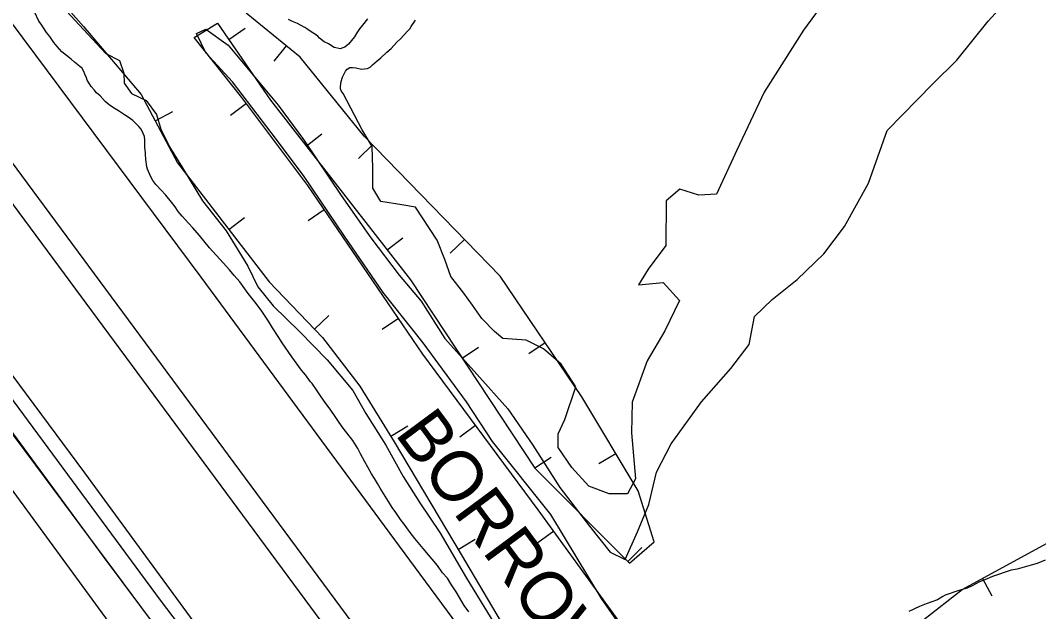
# Model space of a CAD drawing. Extents: x 3263578 to 3301413, y 764927 to 798602.
# Drawn here: x 3286141 to 3287429, y 776533 to 777281 of the extents above; entities that cross this region are included whole.
import ezdxf

# ---------------------------------------------------------------- set-up
doc = ezdxf.new("R2010")
doc.units = 0
for name, color, linetype in [('V-BORW-IDEN', 7, 'Continuous'), ('V-BORW-LINE', 7, 'Continuous'), ('V-LEVE-TOET', 7, 'Continuous'), ('V-ROAD-CNTR', 7, 'Continuous'), ('V-SITE-VEGE', 7, 'Continuous'), ('V-SURV-LINE', 7, 'Continuous'), ('V-TOPO-SHOR', 7, 'Continuous')]:
    doc.layers.add(name, color=color, linetype=linetype)

msp = doc.modelspace()

# ---------------------------------------------------------------- linework, layer by layer
at = {"layer": 'V-BORW-LINE'}
for p, q in [((3286405, 777256.5), (3286425.6, 777270.7)), ((3286477.5, 777248.5), (3286461.7, 777229.1)), ((3286427.2, 777175.5), (3286407.2, 777160.5)), ((3286311.9, 777153.7), (3286334, 777165.4)), ((3286502.8, 777121.8), (3286522.6, 777137.1)), ((3286586.7, 777123.2), (3286568.8, 777105.8)), ((3286525.7, 777041.2), (3286505.1, 777027.1)), ((3286404.9, 777016.1), (3286424.7, 777031.4)), ((3286605.1, 776990.3), (3286624.8, 777005.6)), ((3286702.8, 777003.7), (3286684.9, 776986.3)), ((3286513.4, 776890), (3286531.4, 776907.3)), ((3286619.6, 776903.6), (3286599, 776889.5)), ((3286699.9, 776853.4), (3286720.8, 776867.2)), ((3286805, 776873), (3286784.3, 776859)), ((3286609.9, 776754.7), (3286631.2, 776767.8)), ((3286717, 776768.4), (3286696.9, 776753.6)), ((3286791.8, 776714.5), (3286812.7, 776728.3)), ((3286894.3, 776732.4), (3286872.9, 776719.6)), ((3286815.9, 776634.4), (3286795.6, 776619.7)), ((3286695.1, 776611.5), (3286716.6, 776624.3)), ((3286909.3, 776596.4), (3286927.1, 776614)), ((3287357.8, 776574.7), (3287369.8, 776552.7))]:
    msp.add_line(p, q, dxfattribs=at)
for points in [[(3286160.4, 777342.2), (3286221.4, 777272.9), (3286294.3, 777187.1), (3286340, 777100.4), (3286455.8, 776950.1), (3286523.5, 776879.5), (3286570.8, 776818.2), (3286614.2, 776747.6), (3286698.9, 776605.2), (3286809.6, 776417.4), (3286922.6, 776297), (3287077.5, 776083.5)], [(3287004.7, 776373.8), (3286796.2, 776661.5), (3286650.4, 776858.3), (3286504.8, 777071.9), (3286421.6, 777183.1), (3286361, 777259.1), (3286390.8, 777277.2), (3286457.6, 777179.9), (3286634.5, 776952.5), (3286792.1, 776714.1), (3286911.7, 776594), (3286942.6, 776621), (3286922.4, 776685.4), (3286851.3, 776804.7), (3286748, 776957.2), (3286576.1, 777134.1), (3286495.3, 777234), (3286426.7, 777289.8)], [(3287635.8, 776864.5), (3287745.4, 777082.2), (3287849.5, 777197.7), (3287882.8, 777161.5), (3287924.8, 777006.7), (3287854.3, 776873.2), (3287839.2, 776817.4), (3287909.8, 776759.6), (3287906.6, 776694.7), (3287779.5, 776623.5), (3287722.3, 776563.9), (3287636.3, 776461.8), (3287511.2, 776403.8), (3287441.6, 776389.5), (3287347.5, 776365.9), (3287246.2, 776391.1), (3287218.3, 776420.9), (3287225.5, 776477.1), (3287332.4, 776560.9), (3287439.7, 776619.3), (3287525.1, 776691.8), (3287573.6, 776725.7), (3287635.8, 776864.5)]]:
    msp.add_lwpolyline(points, dxfattribs=at)
at = {"layer": 'V-LEVE-TOET'}
for points in [[(3284126.3, 779529.1), (3284162.9, 779488.4), (3284218.5, 779416.3), (3284353, 779234.8), (3284501.4, 779037.8), (3284646, 778841.6), (3284765.5, 778673.7), (3284949.2, 778430), (3285219, 778068), (3285459.2, 777737.5), (3285691.2, 777424.3), (3285965.8, 777054.1), (3286222.6, 776708.5), (3286385.9, 776484.8), (3286571.9, 776233.4), (3286758.9, 775979.6), (3286871.1, 775830.8)], [(3287161.8, 775830.9), (3287131.1, 775890.3), (3287046.7, 776024.8), (3286938.6, 776189.3), (3286930.1, 776200.3), (3286881.3, 776262.8), (3286620.6, 776615.7), (3286369.9, 776955.7), (3286114.9, 777297.8), (3285934.2, 777538), (3285840, 777634.2), (3285749.6, 777751.3), (3285729.7, 777777.6), (3285706.2, 777802.7), (3285684.1, 777829), (3285660.6, 777857.1), (3285622.8, 777919.3), (3285398.6, 778209.6)]]:
    msp.add_lwpolyline(points, dxfattribs=at)
at = {"layer": 'V-ROAD-CNTR'}
for points in [[(3286817.5, 775833.6), (3286161.1, 776718.1), (3285511.5, 777590.9), (3285032.8, 778237.4), (3284479.5, 778985.2), (3284180.8, 779387.8)], [(3285836.1, 777156.8), (3286022.5, 776906.7), (3286246.2, 776602.6), (3286504.3, 776256.5), (3286568.2, 776171)]]:
    msp.add_lwpolyline(points, dxfattribs=at)
at = {"layer": 'V-SITE-VEGE'}
for p, q in [((3287191.8, 777351), (3287131.4, 777268.3)), ((3287365.3, 777279.9), (3287395.2, 777313.6)), ((3286164.8, 777279.6), (3286159.2, 777291.6)), ((3286189.8, 777303.2), (3286221, 777269.1)), ((3286167.6, 777275.9), (3286164.8, 777279.6)), ((3286635.6, 777273), (3286641.1, 777280.9)), ((3287325.5, 777230.2), (3287365.3, 777279.9)), ((3286174.5, 777265.3), (3286167.6, 777275.9)), ((3286178.7, 777260.2), (3286174.5, 777265.3)), ((3286221, 777269.1), (3286249.3, 777238.9)), ((3286364, 777264.3), (3286375.8, 777269.7)), ((3286375.8, 777269.7), (3286404.1, 777249.5)), ((3286626.4, 777261.9), (3286631.4, 777267.5)), ((3286631.4, 777267.5), (3286633.7, 777270.2)), ((3286633.7, 777270.2), (3286635.6, 777273)), ((3287131.4, 777268.3), (3287081.9, 777189.9)), ((3286183.8, 777252.8), (3286178.7, 777260.2)), ((3286188, 777247.8), (3286183.8, 777252.8)), ((3286376.1, 777239.5), (3286364, 777264.3)), ((3286610.2, 777245.2), (3286617.6, 777253.1)), ((3286617.6, 777253.1), (3286622.2, 777257.3)), ((3286622.2, 777257.3), (3286626.4, 777261.9)), ((3286194, 777240.9), (3286188, 777247.8)), ((3286205.6, 777231.6), (3286194, 777240.9)), ((3286409.5, 777202.9), (3286376.1, 777239.5)), ((3286404.1, 777249.5), (3286467.2, 777173.5)), ((3286597.3, 777233.2), (3286604.7, 777240.6)), ((3286604.7, 777240.6), (3286610.2, 777245.2)), ((3286209.7, 777228), (3286205.6, 777231.6)), ((3286213.9, 777224.7), (3286209.7, 777228)), ((3286249.3, 777238.9), (3286266.6, 777229.8)), ((3286266.6, 777229.8), (3286272.3, 777213.8)), ((3286586.7, 777224.4), (3286592.7, 777229.5)), ((3286592.7, 777229.5), (3286597.3, 777233.2)), ((3287295, 777200.5), (3287325.5, 777230.2)), ((3286217.1, 777222), (3286213.9, 777224.7)), ((3286219, 777220.6), (3286217.1, 777222)), ((3286221.8, 777216), (3286219, 777220.6)), ((3286222.7, 777212.7), (3286221.8, 777216)), ((3286272.3, 777213.8), (3286272.7, 777201.3)), ((3286548.9, 777209), (3286552.6, 777216.4)), ((3286552.6, 777216.4), (3286554.4, 777219.2)), ((3286554.4, 777219.2), (3286558.1, 777221.1)), ((3286558.1, 777221.1), (3286561.3, 777221.1)), ((3286561.3, 777221.1), (3286565.5, 777220.6)), ((3286565.5, 777220.6), (3286572.9, 777219.2)), ((3286572.9, 777219.2), (3286576.1, 777219.3)), ((3286576.1, 777219.3), (3286580.3, 777219.7)), ((3286580.3, 777219.7), (3286583.5, 777221.6)), ((3286583.5, 777221.6), (3286586.7, 777224.4)), ((3286225, 777208.1), (3286222.7, 777212.7)), ((3286226, 777204.9), (3286225, 777208.1)), ((3286228.7, 777200.3), (3286226, 777204.9)), ((3286272.7, 777201.3), (3286281.9, 777188.3)), ((3286458.6, 777139), (3286409.5, 777202.9)), ((3286546.1, 777197), (3286547.1, 777203.5)), ((3286547.1, 777203.5), (3286548.9, 777209)), ((3286231.1, 777197.1), (3286228.7, 777200.3)), ((3286234.8, 777192.9), (3286231.1, 777197.1)), ((3286237.6, 777189.2), (3286234.8, 777192.9)), ((3286242.2, 777185.1), (3286237.6, 777189.2)), ((3286281.9, 777188.3), (3286300.5, 777179.3)), ((3286546.2, 777194.2), (3286546.1, 777197)), ((3286547.1, 777191.5), (3286546.2, 777194.2)), ((3286549.4, 777188.2), (3286547.1, 777191.5)), ((3286573.7, 777142.1), (3286549.4, 777188.2)), ((3287081.9, 777189.9), (3287047.4, 777116.6)), ((3287237.2, 777141.5), (3287295, 777200.5)), ((3286248.7, 777178.2), (3286242.2, 777185.1)), ((3286253.8, 777174), (3286248.7, 777178.2)), ((3286300.5, 777179.3), (3286313.5, 777161.5)), ((3286259.3, 777169.9), (3286253.8, 777174)), ((3286265.3, 777166.2), (3286259.3, 777169.9)), ((3286273.2, 777161.1), (3286265.3, 777166.2)), ((3286467.2, 777173.5), (3286499.4, 777130)), ((3286277.8, 777158.4), (3286273.2, 777161.1)), ((3286283.4, 777154.2), (3286277.8, 777158.4)), ((3286291.3, 777146.4), (3286283.4, 777154.2)), ((3286313.5, 777161.5), (3286319.2, 777143)), ((3286294, 777143.2), (3286291.3, 777146.4)), ((3286296.8, 777137.6), (3286294, 777143.2)), ((3286298.2, 777133.9), (3286296.8, 777137.6)), ((3286319.2, 777143), (3286330.1, 777120.9)), ((3286499.3, 777084.7), (3286458.6, 777139)), ((3286586.3, 777121.2), (3286573.7, 777142.1)), ((3287213.9, 777074.7), (3287237.2, 777141.5)), ((3286298.7, 777129.3), (3286298.2, 777133.9)), ((3286298.7, 777120.1), (3286298.7, 777129.3)), ((3286499.4, 777130), (3286547.2, 777059.2)), ((3286299.7, 777113.6), (3286298.7, 777120.1)), ((3286299.7, 777111.3), (3286299.7, 777113.6)), ((3286300.2, 777104.8), (3286299.7, 777111.3)), ((3286330.1, 777120.9), (3286346.2, 777094.1)), ((3286587, 777093.8), (3286586.3, 777121.2)), ((3287047.4, 777116.6), (3287021.5, 777060.9)), ((3286301.1, 777095.6), (3286300.2, 777104.8)), ((3286302, 777092.4), (3286301.1, 777095.6)), ((3286306.2, 777082.7), (3286302, 777092.4)), ((3286346.2, 777094.1), (3286371.8, 777052.6)), ((3286587, 777068.4), (3286587, 777093.8)), ((3286309, 777078.1), (3286306.2, 777082.7)), ((3286312.7, 777073), (3286309, 777078.1)), ((3286325.2, 777059.6), (3286312.7, 777073)), ((3286551.3, 777007.8), (3286499.3, 777084.7)), ((3287183.6, 777020), (3287213.9, 777074.7)), ((3286332.6, 777050.9), (3286325.2, 777059.6)), ((3286547.2, 777059.2), (3286584.6, 777005.5)), ((3286597.2, 777051.4), (3286587, 777068.4)), ((3286975.4, 777067.2), (3286957.8, 777052.4)), ((3286999.4, 777059.8), (3286975.4, 777067.2)), ((3287021.5, 777060.9), (3286999.4, 777059.8)), ((3286337.3, 777044.9), (3286332.6, 777050.9)), ((3286371.8, 777052.6), (3286401.4, 777014.6)), ((3286623.9, 777047.5), (3286597.2, 777051.4)), ((3286641.1, 777044.3), (3286623.9, 777047.5)), ((3286957.8, 777052.4), (3286957.4, 776995.9)), ((3286341, 777038.9), (3286337.3, 777044.9)), ((3286346.1, 777032.9), (3286341, 777038.9)), ((3286668.4, 777002.6), (3286641.1, 777044.3)), ((3286354, 777024.1), (3286346.1, 777032.9)), ((3286359.5, 777018.2), (3286354, 777024.1)), ((3286367.9, 777008.5), (3286359.5, 777018.2)), ((3286380.4, 776992.8), (3286367.9, 777008.5)), ((3286401.4, 777014.6), (3286429.2, 776969.7)), ((3286600.2, 776936.4), (3286551.3, 777007.8)), ((3287157.5, 776985.2), (3287183.6, 777020)), ((3286584.6, 777005.5), (3286620.5, 776958.3)), ((3286678.1, 776978.1), (3286668.4, 777002.6)), ((3286957.4, 776995.9), (3286935, 776966)), ((3286398, 776973.9), (3286380.4, 776992.8)), ((3287123.7, 776953), (3287157.5, 776985.2)), ((3286405.9, 776965.2), (3286398, 776973.9)), ((3286429.2, 776969.7), (3286441.8, 776943.7)), ((3286685.5, 776956.8), (3286678.1, 776978.1)), ((3286411.9, 776958.2), (3286405.9, 776965.2)), ((3286418.8, 776949.9), (3286411.9, 776958.2)), ((3286620.5, 776958.3), (3286648.2, 776925.5)), ((3286702, 776935.6), (3286685.5, 776956.8)), ((3286935, 776966), (3286922.8, 776946)), ((3286429.5, 776935.2), (3286418.8, 776949.9)), ((3286441.8, 776943.7), (3286460.9, 776919.6)), ((3286922.8, 776946), (3286954, 776949.1)), ((3286954, 776949.1), (3286974.9, 776926.3)), ((3287092.1, 776927.5), (3287123.7, 776953)), ((3286437.9, 776924.6), (3286429.5, 776935.2)), ((3286650.9, 776872.9), (3286600.2, 776936.4)), ((3286712.9, 776920.4), (3286702, 776935.6)), ((3286445.7, 776914), (3286437.9, 776924.6)), ((3286460.9, 776919.6), (3286494.3, 776887.2)), ((3286648.2, 776925.5), (3286677.9, 776878.1)), ((3286724.7, 776903.6), (3286712.9, 776920.4)), ((3286974.9, 776926.3), (3286956.2, 776887.9)), ((3287069.8, 776906.1), (3287092.1, 776927.5)), ((3286455, 776900.1), (3286445.7, 776914)), ((3287062.9, 776870.7), (3287069.8, 776906.1)), ((3286460.1, 776891.8), (3286455, 776900.1)), ((3286467.5, 776880.8), (3286460.1, 776891.8)), ((3286741, 776887.3), (3286724.7, 776903.6)), ((3286472.6, 776872.9), (3286467.5, 776880.8)), ((3286494.3, 776887.2), (3286529.1, 776851.3)), ((3286751.5, 776878.2), (3286741, 776887.3)), ((3286956.2, 776887.9), (3286933.8, 776849.9)), ((3286484.7, 776854.9), (3286472.6, 776872.9)), ((3286705.4, 776798), (3286650.9, 776872.9)), ((3286677.9, 776878.1), (3286718.7, 776833)), ((3286780.8, 776876.3), (3286751.5, 776878.2)), ((3286802.8, 776865.2), (3286780.8, 776876.3)), ((3287039.8, 776840.5), (3287062.9, 776870.7)), ((3286496.8, 776838.3), (3286484.7, 776854.9)), ((3286825.2, 776845.7), (3286802.8, 776865.2)), ((3286529.1, 776851.3), (3286561.6, 776812.5)), ((3286843.6, 776817.1), (3286825.2, 776845.7)), ((3286933.8, 776849.9), (3286915.1, 776797.7)), ((3287002.8, 776798.3), (3287039.8, 776840.5)), ((3286501.9, 776832.4), (3286496.8, 776838.3)), ((3286508.4, 776823.6), (3286501.9, 776832.4)), ((3286718.7, 776833), (3286757.6, 776789.2)), ((3286510.2, 776821.3), (3286508.4, 776823.6)), ((3286516.7, 776812.1), (3286510.2, 776821.3)), ((3286829.8, 776775.9), (3286843.6, 776817.1)), ((3286520.9, 776805.6), (3286516.7, 776812.1)), ((3286527.8, 776795.9), (3286520.9, 776805.6)), ((3286561.6, 776812.5), (3286578.2, 776783.5)), ((3286532.9, 776789), (3286527.8, 776795.9)), ((3286540.4, 776778.4), (3286532.9, 776789)), ((3286738.4, 776748.1), (3286705.4, 776798)), ((3286757.6, 776789.2), (3286789.2, 776743.4)), ((3286915.1, 776797.7), (3286914.3, 776758.8)), ((3286964.3, 776745.2), (3287002.8, 776798.3)), ((3286544.5, 776772), (3286540.4, 776778.4)), ((3286578.2, 776783.5), (3286603.4, 776743.3)), ((3286821.6, 776757.7), (3286829.8, 776775.9)), ((3286549.6, 776765), (3286544.5, 776772)), ((3286561.7, 776749.4), (3286549.6, 776765)), ((3286821.5, 776740.2), (3286821.6, 776757.7)), ((3286914.3, 776758.8), (3286919, 776700.8)), ((3286568.2, 776739.2), (3286561.7, 776749.4)), ((3286571.4, 776732.3), (3286568.2, 776739.2)), ((3286603.4, 776743.3), (3286625.6, 776703.6)), ((3286812, 776655.5), (3286738.4, 776748.1)), ((3286789.2, 776743.4), (3286823.6, 776689.9)), ((3286838.8, 776715.1), (3286821.5, 776740.2)), ((3286945.8, 776709), (3286964.3, 776745.2)), ((3286577, 776722.1), (3286571.4, 776732.3)), ((3286580.7, 776715.7), (3286577, 776722.1)), ((3286585.4, 776706.9), (3286580.7, 776715.7)), ((3286860, 776691.6), (3286838.8, 776715.1)), ((3286589.1, 776701.4), (3286585.4, 776706.9)), ((3286592.8, 776694.9), (3286589.1, 776701.4)), ((3286625.6, 776703.6), (3286646.4, 776670.3)), ((3286919, 776700.8), (3286908.9, 776681.7)), ((3286935.9, 776668.2), (3286945.8, 776709)), ((3286596.5, 776688.9), (3286592.8, 776694.9)), ((3286606.7, 776671.9), (3286596.5, 776688.9)), ((3286823.6, 776689.9), (3286861.1, 776640.9)), ((3286886, 776682), (3286860, 776691.6)), ((3286908.9, 776681.7), (3286886, 776682)), ((3286611.4, 776664.5), (3286606.7, 776671.9)), ((3286616, 776658), (3286611.4, 776664.5)), ((3286646.4, 776670.3), (3286671.6, 776632.7)), ((3286921.5, 776633.7), (3286935.9, 776668.2)), ((3286622, 776649.3), (3286616, 776658)), ((3286626.7, 776643.3), (3286622, 776649.3)), ((3286876.2, 776549.2), (3286812, 776655.5)), ((3286634.1, 776632.7), (3286626.7, 776643.3)), ((3286861.1, 776640.9), (3286887, 776607.8)), ((3286640.1, 776625.3), (3286634.1, 776632.7)), ((3286650.8, 776612.8), (3286640.1, 776625.3)), ((3286671.6, 776632.7), (3286705.6, 776575.2)), ((3286906.2, 776598.9), (3286921.5, 776633.7)), ((3286668.8, 776591.2), (3286650.8, 776612.8)), ((3286887, 776607.8), (3286906.2, 776598.9)), ((3287437.1, 776597.9), (3287427, 776593.7)), ((3286675.3, 776582), (3286668.8, 776591.2)), ((3287394.2, 776585.3), (3287370.7, 776577.4)), ((3287401.6, 776586.7), (3287394.2, 776585.3)), ((3287419.6, 776591.4), (3287401.6, 776586.7)), ((3287427, 776593.7), (3287419.6, 776591.4)), ((3286681.4, 776575), (3286675.3, 776582)), ((3286685.5, 776568.1), (3286681.4, 776575)), ((3286705.6, 776575.2), (3286751.2, 776500.9)), ((3287354.1, 776570.4), (3287344.8, 776565.3)), ((3287361, 776573.2), (3287354.1, 776570.4)), ((3287370.7, 776577.4), (3287361, 776573.2)), ((3286692.5, 776558), (3286685.5, 776568.1)), ((3286702.7, 776540.5), (3286692.5, 776558)), ((3287328.2, 776559.7), (3287310.7, 776553.7)), ((3287338.4, 776562.5), (3287328.2, 776559.7)), ((3287344.8, 776565.3), (3287338.4, 776562.5)), ((3286929.2, 776474.2), (3286876.2, 776549.2)), ((3287301, 776547.6), (3287286.7, 776542.5)), ((3287307.9, 776551.8), (3287301, 776547.6)), ((3287310.7, 776553.7), (3287307.9, 776551.8)), ((3286708.3, 776532.6), (3286702.7, 776540.5)), ((3287278.4, 776539.3), (3287265, 776532.8)), ((3287286.7, 776542.5), (3287278.4, 776539.3))]:
    msp.add_line(p, q, dxfattribs=at)
msp.add_lwpolyline([(3286580.1, 777282.6), (3286574.1, 777274.7), (3286570.4, 777270.1), (3286566.8, 777265), (3286564, 777259.9), (3286556.2, 777250.6), (3286554.3, 777248.8), (3286551.6, 777246.9), (3286547.9, 777245.5), (3286546, 777244.6), (3286538.2, 777246.4), (3286531.2, 777251), (3286525.7, 777253.8), (3286519.6, 777258.4), (3286517.3, 777260.7), (3286514.6, 777263), (3286509, 777266.2), (3286504.8, 777269), (3286501.1, 777271.7), (3286495.6, 777274.5), (3286491.9, 777276.8), (3286485.4, 777279.5), (3286480.3, 777281.8)], dxfattribs=at)
at = {"layer": 'V-SURV-LINE'}
for points in [[(3285916.7, 777390.2), (3287068.6, 775830.8)], [(3287031.3, 775830.8), (3285892.6, 777372.4)]]:
    msp.add_lwpolyline(points, dxfattribs=at)
at = {"layer": 'V-TOPO-SHOR'}
for points in [[(3286853, 775830.9), (3286438.5, 776389.2), (3286318.7, 776547.3), (3285959.4, 777033.7), (3285715, 777359.6), (3285441.9, 777723.8)], [(3286306.8, 776446.7), (3285947.4, 776937.9), (3285834.8, 777093.6)]]:
    msp.add_lwpolyline(points, dxfattribs=at)

# ---------------------------------------------------------------- texts
at = {"layer": 'V-BORW-IDEN'}
msp.add_text('BORROW PIT', height=64, rotation=306.5596, dxfattribs=at).set_placement((3286613.9, 776757.8))

doc.saveas('drawing.dxf')
